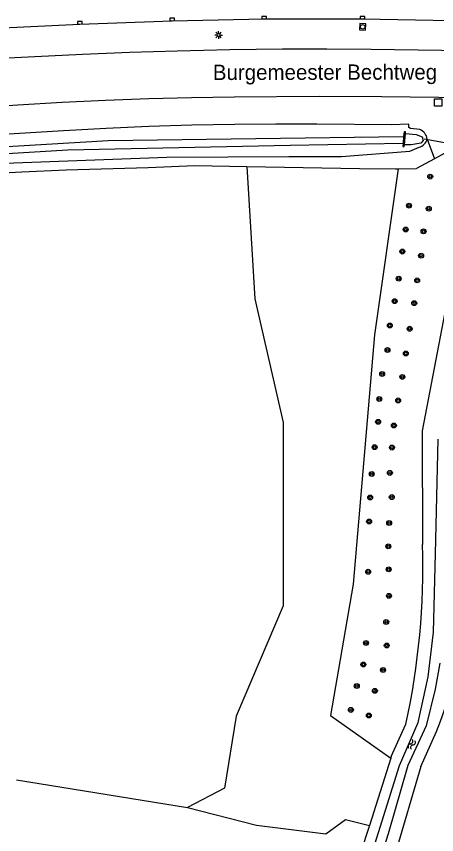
# Model space of a CAD drawing. Extents: x 133000 to 136000, y 400500 to 403500.
# Drawn here: x 134063.3 to 134131.9, y 401043.6 to 401177.3 of the extents above; entities that cross this region are included whole.
import ezdxf

# ---------------------------------------------------------------- set-up
doc = ezdxf.new("R2010")
doc.units = 0
for name, color, linetype in [('gg-afsc-faunaraster', 7, 'Continuous'), ('gg-anno-openbare ruimte label', 7, 'Continuous'), ('gg-knt-verharding', 7, 'Continuous'), ('gg-kntw-bovenkant insteek waterloop', 7, 'Continuous'), ('gg-kntw-waterlijn', 7, 'Continuous'), ('gg-kwrk-duiker nz buis', 7, 'Continuous'), ('gg-kwrk-kunstwerk', 7, 'Continuous'), ('gt-grn-groengrens', 7, 'Continuous'), ('gt-symb-boom', 7, 'Continuous'), ('gt-symb-hm paal', 7, 'Continuous'), ('gt-symb-kolk', 7, 'Continuous'), ('gt-symb-lichtmast', 7, 'Continuous'), ('gt-symb-rioolschacht', 7, 'Continuous'), ('gt-symb-watersymbool', 7, 'Continuous')]:
    doc.layers.add(name, color=color, linetype=linetype)

# ---------------------------------------------------------------- blocks, each defined once
blk = doc.blocks.new('gt0-WA')
at = {"layer": 'gt-symb-watersymbool'}
for centre, start, end in [((-0.32, 0.02), 28.0725, 151.9275), ((0.43, 0.42), 208.0725, 331.9275), ((-0.32, -0.43), 28.0725, 151.9275), ((0.43, -0.03), 208.0725, 331.9275)]:
    blk.add_arc(centre, 0.425, start, end, dxfattribs=at)
blk = doc.blocks.new('gt0-BOOM')
at = {"layer": 'gt-symb-boom'}
for radius in [0.4, 0.2]:
    blk.add_circle((0, 0), radius, dxfattribs=at)
blk = doc.blocks.new('gt0-HMpaal')
at = {"layer": 'gt-symb-hm paal'}
blk.add_lwpolyline([(-0.6, 0.6), (0.6, 0.6), (0.6, -0.6), (-0.6, -0.6)], close=True, dxfattribs=at)
blk = doc.blocks.new('gt0-LMAST')
at = {"layer": 'gt-symb-lichtmast'}
for p, q in [((-0.18, 0.17), (-0.45, 0.44)), ((-0.01, 0.25), (-0.01, 0.62)), ((0.17, 0.17), (0.44, 0.44)), ((-0.26, 0), (-0.63, 0)), ((-0.18, -0.18), (-0.45, -0.45)), ((-0.01, -0.25), (-0.01, -0.63)), ((0.44, -0.45), (0.17, -0.18)), ((0.24, 0), (0.62, 0))]:
    blk.add_line(p, q, dxfattribs=at)
blk.add_circle((-0.01, 0), 0.25, dxfattribs=at)
blk = doc.blocks.new('gt0-RS')
at = {"layer": 'gt-symb-rioolschacht'}
blk.add_lwpolyline([(-0.5, -0.5), (0.5, -0.5), (0.5, 0.5), (-0.5, 0.5)], close=True, dxfattribs=at)
blk.add_circle((0, 0), 0.375, dxfattribs=at)
blk = doc.blocks.new('gt0-KOLK')
at = {"layer": 'gt-symb-kolk'}
blk.add_lwpolyline([(0, 0), (0.38, 0), (0.38, 0.4), (-0.37, 0.4), (-0.37, 0), (0, 0)], dxfattribs=at)

msp = doc.modelspace()

# ---------------------------------------------------------------- linework, layer by layer
at = {"layer": 'gg-afsc-faunaraster'}
for p, q in [((134131.54, 401154.05), (134128.62, 401152.44)), ((134092.4, 401152.94), (134100.91, 401152.79)), ((134125.64, 401152.4), (134128.62, 401152.44))]:
    msp.add_line(p, q, dxfattribs=at)
for points in [[(134144.24, 401157.74), (134141.86, 401157.94), (134139.16, 401158.24), (134131.54, 401154.05)], [(134001.4, 401145.89), (134009.01, 401146.89), (134015.57, 401147.71), (134029.86, 401149.23), (134036.3, 401149.88), (134042.74, 401150.47), (134049.86, 401151.04), (134056.99, 401151.53), (134064.2, 401151.92), (134071.41, 401152.23), (134084.82, 401152.64), (134092.4, 401152.94)], [(134100.91, 401152.79), (134119.31, 401152.45), (134125.17, 401152.39), (134125.64, 401152.4)]]:
    msp.add_lwpolyline(points, dxfattribs=at)
at = {"layer": 'gg-knt-verharding'}
for points in [[(133863.67, 401141.73), (133878.69, 401145.85), (133893.66, 401149.79), (133908.68, 401153.42), (133923.63, 401156.73), (133938.69, 401159.84), (133949.02, 401161.88), (133953.64, 401162.73), (133968.73, 401165.09), (133985.47, 401167.84), (133998.78, 401169.62), (134013.78, 401171.41), (134028.9, 401172.97), (134043.67, 401174.23), (134058.77, 401175.31), (134073.66, 401176.07), (134088.72, 401176.61), (134103.72, 401176.89), (134119.8, 401176.91), (134137.11, 401176.61)], [(134163.85, 401170.73), (134140.34, 401171.64), (134121.22, 401171.92), (134113.97, 401171.97), (134106.72, 401171.96), (134098.14, 401171.83), (134089.55, 401171.63), (134081.83, 401171.39), (134074.11, 401171.09), (134066.33, 401170.73), (134058.56, 401170.3), (134051.55, 401169.82), (134044.55, 401169.28), (134030.02, 401168.01), (134014.96, 401166.51), (134007.56, 401165.7), (134000, 401164.71)], [(134194.47, 401161.3), (134184.94, 401161.97), (134171.45, 401162.72), (134136.9, 401163.99), (134122.94, 401164.18), (134112.7, 401164.2), (134098.86, 401164.12), (134091.89, 401164.01), (134084.93, 401163.83), (134077.86, 401163.57), (134070.79, 401163.23), (134063.51, 401162.82), (134057.07, 401162.39)]]:
    msp.add_lwpolyline(points, dxfattribs=at)
at = {"layer": 'gg-kntw-bovenkant insteek waterloop'}
for p, q in [((134124.5, 401056.39), (134126.86, 401061.69)), ((134129.33, 401054.76), (134131.89, 401060.46)), ((134124.42, 401056.13), (134120.91, 401045.15)), ((134124.5, 401056.39), (134124.42, 401056.13)), ((134129.33, 401054.76), (134113.09, 401000)), ((134120.91, 401045.15), (134110.18, 401011.6))]:
    msp.add_line(p, q, dxfattribs=at)
for points in [[(134129.13, 401158.82), (134127.64, 401159.02), (134127.37, 401159.17), (134127.37, 401159.71), (134124.57, 401159.59), (134112.36, 401159.68), (134105.66, 401159.7), (134098.95, 401159.67), (134091.93, 401159.55), (134084.92, 401159.34), (134077.96, 401159.01), (134071, 401158.61), (134049.45, 401157.3), (134042.42, 401156.79), (134035.87, 401156.2), (134029.33, 401155.55), (134008.64, 401153.34), (134003.49, 401152.72), (134000, 401152.26), (133986.17, 401150.35)], [(134116.39, 401154.43), (134127.5, 401155.29), (134129.03, 401155.93)], [(134005.95, 401148.25), (134026.93, 401150.53), (134040.75, 401152.04), (134061.43, 401153.33), (134087.83, 401154.3), (134107.76, 401154.43), (134116.39, 401154.43)], [(134138.12, 401154.52), (134129.55, 401109.62), (134129.6, 401091.02)]]:
    msp.add_lwpolyline(points, dxfattribs=at)
for centre, radius, start, end in [((134128.41, 401156.96), 1.99, 9.2404, 68.8038), ((134128.48, 401157.81), 1.96, 286.2379, 344.3999), ((134009.22, 401087.47), 120.44, 347.6384, 1.6867), ((134074.05, 401082.94), 62.06, 338.7579, 5.438)]:
    msp.add_arc(centre, radius, start, end, dxfattribs=at)
at = {"layer": 'gg-kntw-waterlijn'}
for points in [[(133970.81, 401145.24), (133971.25, 401145.69), (133979.91, 401147.29), (133987.92, 401148.51), (134000.94, 401150.48), (134019.1, 401152.42), (134042.52, 401154.91), (134078.3, 401157.06), (134126.51, 401157.67)], [(134126.82, 401158.17), (134128.54, 401158.03), (134129.56, 401157.62), (134129.68, 401157.04), (134129.29, 401156.6), (134127.74, 401156.33), (134126.63, 401156.34)], [(133970.81, 401145.24), (133971.4, 401144.82), (133979.86, 401146.46), (134001.65, 401149.54), (134040.27, 401153.61), (134071.62, 401155.51), (134107.97, 401156.25), (134126.41, 401156.62)], [(134095.43, 400959.75), (134102.92, 400981.91), (134119.25, 401033.91), (134125.85, 401054.92), (134128.89, 401061.95), (134130.49, 401069.44), (134131.38, 401076.71), (134131.69, 401089.52), (134132.14, 401108.26)], [(134132.42, 401071.66), (134131.65, 401067.39), (134130.17, 401061.42), (134127.19, 401054.92), (134123.99, 401043.78), (134119.01, 401027.92), (134113.83, 401010.7), (134106.8, 400987.47), (134097.85, 400959.2), (134096.9, 400959.2), (134095.43, 400959.75)]]:
    msp.add_lwpolyline(points, dxfattribs=at)
at = {"layer": 'gg-kwrk-duiker nz buis'}
msp.add_line((134139.13, 401155.55), (134129.88, 401157.25), dxfattribs=at)
at = {"layer": 'gg-kwrk-kunstwerk'}
for p, q in [((134126.51, 401157.67), (134126.41, 401156.62)), ((134126.63, 401156.34), (134126.82, 401158.17)), ((134126.41, 401156.62), (134126.36, 401156.07))]:
    msp.add_line(p, q, dxfattribs=at)
for points in [[(134126.82, 401158.17), (134126.84, 401158.46), (134126.58, 401158.46), (134126.51, 401157.67)], [(134126.36, 401156.07), (134126.6, 401156.08), (134126.63, 401156.34)]]:
    msp.add_lwpolyline(points, dxfattribs=at)
at = {"layer": 'gt-grn-groengrens'}
for p, q in [((134130.37, 401157.28), (134131.54, 401154.05)), ((134063.3, 401052.56), (134091.21, 401048.05))]:
    msp.add_line(p, q, dxfattribs=at)
for points in [[(134100.91, 401152.79), (134102.21, 401131.17), (134106.83, 401110.94), (134106.83, 401081), (134099.17, 401062.98), (134097.25, 401051.2), (134091.21, 401048.05)], [(134125.64, 401152.4), (134121.75, 401125.3), (134118.28, 401084.55), (134114.56, 401063.12), (134124.42, 401056.13)], [(134091.21, 401048.05), (134102.51, 401045.19), (134113.8, 401043.74), (134117.03, 401046.12), (134120.91, 401045.15)]]:
    msp.add_lwpolyline(points, dxfattribs=at)

# ---------------------------------------------------------------- block references
at = {"layer": 'gt-symb-boom'}
for p in [(134130.85, 401151.14), (134127.39, 401146.39), (134130.61, 401145.91), (134126.85, 401142.49), (134129.76, 401142.2), (134126.3, 401138.89), (134129.36, 401138.23), (134125.71, 401134.47), (134128.71, 401134.18), (134125.04, 401130.79), (134128.24, 401130.47), (134124.25, 401126.81), (134127.49, 401126.28), (134123.88, 401122.82), (134126.86, 401122.24), (134123.01, 401118.88), (134126.3, 401118.41), (134122.53, 401114.8), (134125.62, 401114.57), (134122.34, 401111.07), (134124.92, 401110.48), (134121.77, 401106.94), (134124.6, 401106.87), (134121.3, 401102.55), (134124.27, 401102.73), (134121.04, 401098.72), (134124.57, 401098.78), (134120.87, 401094.79), (134124.15, 401094.54), (134124.01, 401090.74), (134120.72, 401086.58), (134124.07, 401086.97), (134124.11, 401082.64), (134123.67, 401078.38), (134120.36, 401074.95), (134123.75, 401074.54), (134119.93, 401071.43), (134123.15, 401070.52), (134118.86, 401067.91), (134121.82, 401067.12), (134117.9, 401064.01), (134120.83, 401063.1)]:
    msp.add_blockref('gt0-BOOM', p, dxfattribs=at)
at = {"layer": 'gt-symb-hm paal'}
msp.add_blockref('gt0-HMpaal', (134132.14, 401163.26), dxfattribs=at)
at = {"layer": 'gt-symb-kolk'}
for p, rotation in [((134073.66, 401176.07), 2.0638197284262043), ((134088.72, 401176.61), 1.088488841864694), ((134103.72, 401176.89), 0.05729576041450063), ((134119.8, 401176.91), -1.0312126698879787)]:
    msp.add_blockref('gt0-KOLK', p, dxfattribs=dict(at, rotation=rotation))
at = {"layer": 'gt-symb-lichtmast'}
msp.add_blockref('gt0-LMAST', (134096.31, 401174.27), dxfattribs=at)
at = {"layer": 'gt-symb-rioolschacht', "rotation": -3.554888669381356}
msp.add_blockref('gt0-RS', (134119.82, 401175.61), dxfattribs=at)
at = {"layer": 'gt-symb-watersymbool', "rotation": 65.99680974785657}
msp.add_blockref('gt0-WA', (134127.8, 401058.32), dxfattribs=at)

# ---------------------------------------------------------------- texts
at = {"layer": 'gg-anno-openbare ruimte label'}
msp.add_text('Burgemeester Bechtweg', height=2.5, rotation=0.1, dxfattribs=at).set_placement((134095.37, 401166.92))

doc.saveas('drawing.dxf')
